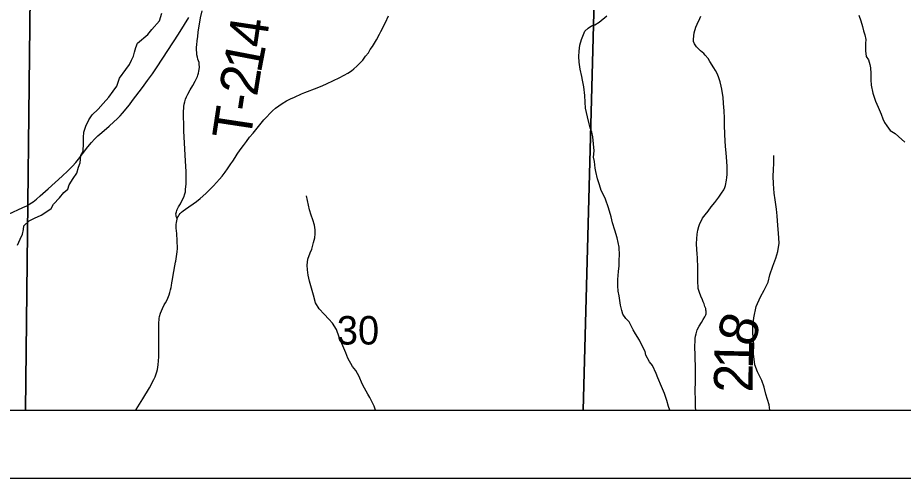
# Model space of a CAD drawing. Extents: x -19.9 to 41.9, y 0 to 32.3.
# Drawn here: x 4.967 to 6.268, y 14 to 14.677 of the extents above; entities that cross this region are included whole.
import ezdxf

# ---------------------------------------------------------------- set-up
doc = ezdxf.new("R2010")
doc.units = 0
for name, color, linetype in [('GM_X_Corporation', 7, 'Continuous'), ('GM_X_Minor_River', 7, 'Continuous'), ('GM_X_Section_Text', 7, 'Continuous'), ('GM_X_Township_Road', 7, 'Continuous'), ('GM_X_Township_Road_Text', 7, 'Continuous'), ('SH_Data', 7, 'Continuous')]:
    doc.layers.add(name, color=color, linetype=linetype)

msp = doc.modelspace()

# ---------------------------------------------------------------- linework, layer by layer
at = {"layer": 'GM_X_Corporation'}
for points in [[(2.1, 17.918), (2.1, 14.1), (8.9, 14.1), (8.9, 17.8974), (7.9072, 17.9171), (7.5529, 17.9242), (7.3858, 17.9277), (6.9468, 17.937), (6.7, 17.9422), (6.3069, 17.9505), (6.2497, 17.9517), (6.2397, 17.9517), (5.9048, 17.9534), (5.761, 17.9543), (5.4954, 17.9559), (5.0257, 17.9637), (5.0192, 17.8403), (4.9169, 17.8392), (4.2613, 17.8672), (3.984, 17.879), (3.7505, 17.884), (2.973, 17.9007), (2.4715, 17.9106)], [(4.9783, 14.1), (5.7974, 14.1), (5.8188, 14.9036), (4.9872, 14.9075), (4.9863, 14.8396)], [(5.7974, 14.1), (6.8053, 14.1), (6.8226, 14.894), (5.8188, 14.9036)], [(3.9655, 14.1), (4.9783, 14.1), (4.9863, 14.8396), (3.9837, 14.8466)]]:
    msp.add_lwpolyline(points, close=True, dxfattribs=at)
msp.add_lwpolyline([(2.1, 17.918), (2.1, 14.1), (7.8246, 14.1), (7.8518, 15.3043), (7.854, 15.4058), (7.8702, 16.1679), (7.8776, 16.5173), (7.9012, 17.4524), (7.9072, 17.9171)], dxfattribs=at)
at = {"layer": 'GM_X_Minor_River'}
for points in [[(4.9665, 14.3425), (4.9705, 14.3517), (4.9738, 14.3586), (4.9753, 14.3655), (4.9759, 14.3712), (4.9834, 14.3782), (4.9913, 14.3825), (5.0011, 14.3868), (5.0093, 14.3919), (5.0157, 14.3965), (5.0194, 14.4027), (5.028, 14.4123), (5.0343, 14.42), (5.0403, 14.4251), (5.0424, 14.4312), (5.048, 14.4408), (5.0535, 14.4485), (5.0561, 14.4573), (5.0586, 14.4638), (5.0596, 14.4744), (5.0629, 14.4802), (5.0635, 14.4924), (5.0634, 14.5008), (5.064, 14.5088), (5.0665, 14.5176), (5.0713, 14.5271), (5.0758, 14.5344), (5.0851, 14.5426), (5.0922, 14.5511), (5.1004, 14.5603), (5.1067, 14.5688), (5.1123, 14.5761), (5.1163, 14.588), (5.1255, 14.601), (5.1307, 14.6083), (5.134, 14.6145), (5.137, 14.6202), (5.138, 14.6263), (5.1402, 14.6332), (5.1428, 14.6397), (5.1577, 14.6521), (5.1637, 14.6598), (5.1748, 14.6722), (5.1785, 14.6836)], [(5.9247, 14.1), (5.9229, 14.1054), (5.9205, 14.1145), (5.9169, 14.1244), (5.9126, 14.1349), (5.9071, 14.1478), (5.9047, 14.1539), (5.8993, 14.1656), (5.8946, 14.1712), (5.8896, 14.181), (5.8884, 14.1864), (5.8852, 14.1928), (5.8802, 14.203), (5.8744, 14.2124), (5.8709, 14.2184), (5.865, 14.2298), (5.86, 14.235), (5.8558, 14.2414), (5.8542, 14.2464), (5.8522, 14.2547), (5.8501, 14.2684), (5.8488, 14.2752), (5.8483, 14.2828), (5.8482, 14.2923), (5.8492, 14.3041), (5.8502, 14.3122), (5.8504, 14.3209), (5.8507, 14.3278), (5.8502, 14.3396), (5.8473, 14.3532), (5.8441, 14.3646), (5.8406, 14.3756), (5.8385, 14.3843), (5.8346, 14.3976), (5.8302, 14.4104), (5.8279, 14.4157), (5.824, 14.4229), (5.8212, 14.4312), (5.8184, 14.44), (5.816, 14.451), (5.8152, 14.4559), (5.8139, 14.4658), (5.8126, 14.4718), (5.8133, 14.4814), (5.8127, 14.4916), (5.8115, 14.5019), (5.8102, 14.5087), (5.8079, 14.5152), (5.8063, 14.5212), (5.8038, 14.5311), (5.801, 14.544), (5.8005, 14.5527), (5.7996, 14.5626), (5.7983, 14.5755), (5.7966, 14.585), (5.7954, 14.5907), (5.793, 14.6013), (5.7917, 14.6116), (5.7908, 14.62), (5.7914, 14.6276), (5.7925, 14.6367), (5.795, 14.6451), (5.7997, 14.657), (5.8046, 14.6616), (5.8095, 14.6648), (5.8143, 14.6667), (5.8211, 14.6706), (5.8323, 14.6796)], [(6.2026, 14.6805), (6.2054, 14.6722), (6.2077, 14.6642), (6.2094, 14.6578), (6.2113, 14.6517), (6.2126, 14.6449), (6.2123, 14.6392), (6.212, 14.6342), (6.2121, 14.6281), (6.2133, 14.6201), (6.2164, 14.6149), (6.2184, 14.6084), (6.2196, 14.6031), (6.2201, 14.5951), (6.2202, 14.5856), (6.2207, 14.578), (6.2228, 14.5662), (6.2268, 14.5545), (6.2307, 14.5454), (6.235, 14.5352), (6.2377, 14.5284), (6.2401, 14.5227), (6.2436, 14.5178), (6.2486, 14.5114), (6.2555, 14.5066), (6.2605, 14.5025), (6.27, 14.4939)], [(6.0716, 14.1), (6.0705, 14.1079), (6.0659, 14.1235), (6.0633, 14.1341), (6.0598, 14.1436), (6.0537, 14.1565), (6.0495, 14.1668), (6.0476, 14.1827), (6.0479, 14.1968), (6.0468, 14.2131), (6.0464, 14.223), (6.0479, 14.2359), (6.0517, 14.2526), (6.0578, 14.2667), (6.0635, 14.2765), (6.0692, 14.2883), (6.0718, 14.299), (6.076, 14.3119), (6.0806, 14.3233), (6.0832, 14.3331), (6.0851, 14.3457), (6.0844, 14.3605), (6.0836, 14.3715), (6.0824, 14.3859), (6.0813, 14.3954), (6.0793, 14.4095), (6.0782, 14.4193), (6.077, 14.4326), (6.0766, 14.444), (6.077, 14.4535), (6.0774, 14.4634), (6.0774, 14.4744)], [(5.4924, 14.1), (5.4901, 14.1059), (5.4839, 14.1188), (5.4812, 14.1237), (5.4761, 14.1327), (5.4726, 14.1388), (5.4683, 14.1494), (5.4636, 14.1584), (5.4586, 14.1641), (5.4516, 14.1765), (5.4485, 14.1845), (5.4442, 14.1947), (5.4391, 14.2076), (5.4351, 14.2185), (5.4293, 14.228), (5.4235, 14.234), (5.417, 14.2411), (5.4093, 14.249), (5.4043, 14.258), (5.4011, 14.269), (5.3983, 14.2796), (5.3955, 14.2895), (5.3934, 14.2986), (5.3926, 14.3062), (5.3921, 14.3134), (5.3931, 14.3222), (5.3964, 14.3314), (5.3986, 14.3367), (5.4011, 14.3467), (5.4032, 14.3536), (5.4039, 14.3593), (5.4038, 14.3654), (5.4026, 14.3718), (5.4002, 14.3798), (5.3978, 14.3866), (5.3954, 14.3945), (5.3907, 14.4154)]]:
    msp.add_lwpolyline(points, dxfattribs=at)
at = {"layer": 'GM_X_Township_Road'}
for points in [[(4.9533, 14.3884), (4.9744, 14.398), (4.9799, 14.4006), (4.9845, 14.4033), (4.9892, 14.4063), (4.9941, 14.4102), (4.9995, 14.415), (5.0115, 14.4256), (5.0319, 14.444), (5.0401, 14.4517), (5.0472, 14.4586), (5.0521, 14.4642), (5.0561, 14.4689), (5.062, 14.4768), (5.0696, 14.487), (5.075, 14.4934), (5.0796, 14.4983), (5.0846, 14.5033), (5.0902, 14.5084), (5.1012, 14.5177), (5.1081, 14.5238), (5.113, 14.5285), (5.1171, 14.5328), (5.1205, 14.5367), (5.1307, 14.549), (5.1355, 14.5553), (5.15, 14.5746), (5.1574, 14.5845), (5.1646, 14.5944), (5.1715, 14.6046), (5.2031, 14.6526), (5.2119, 14.6668), (5.2182, 14.6773)], [(5.2009, 14.381), (5.2002, 14.3828), (5.1995, 14.3848), (5.1993, 14.3866), (5.1992, 14.3885), (5.1993, 14.3902), (5.1997, 14.3917), (5.2003, 14.3934), (5.201, 14.3949), (5.203, 14.3988), (5.2057, 14.4036), (5.2085, 14.409), (5.211, 14.4143), (5.2118, 14.4164), (5.2131, 14.4212), (5.2134, 14.4244), (5.2138, 14.4289), (5.214, 14.4323), (5.2141, 14.4349), (5.2143, 14.4388), (5.2141, 14.4439), (5.2139, 14.4502), (5.2131, 14.4665), (5.2109, 14.5103), (5.2107, 14.5163), (5.2102, 14.5359), (5.2104, 14.5399), (5.2105, 14.5435), (5.2106, 14.5466), (5.2111, 14.5501), (5.2121, 14.5534), (5.2133, 14.5574), (5.2147, 14.5608), (5.2165, 14.5645), (5.2199, 14.571), (5.2237, 14.5772), (5.2273, 14.5838), (5.2306, 14.5904), (5.2313, 14.5923), (5.2323, 14.5955), (5.2329, 14.5982), (5.2333, 14.601), (5.2336, 14.6042), (5.2334, 14.6088), (5.2331, 14.611), (5.2322, 14.6138), (5.2315, 14.6162), (5.2307, 14.6192), (5.23, 14.6223), (5.2296, 14.6251), (5.2294, 14.6295), (5.2295, 14.6339), (5.2297, 14.6371), (5.2302, 14.6431), (5.2311, 14.6494), (5.2318, 14.6558), (5.2331, 14.6649), (5.234, 14.6705), (5.2353, 14.6769), (5.2375, 14.6872)], [(5.4982, 14.653), (5.5, 14.6565), (5.5068, 14.6698), (5.5114, 14.6796)], [(5.9628, 14.1), (5.9626, 14.1045), (5.9623, 14.1095), (5.9622, 14.1162), (5.9621, 14.127), (5.9623, 14.1441), (5.9625, 14.1619), (5.9621, 14.1789), (5.9616, 14.1952), (5.9618, 14.201), (5.9619, 14.2054), (5.9625, 14.2087), (5.9633, 14.2123), (5.9649, 14.2181), (5.9677, 14.2237), (5.971, 14.229), (5.9739, 14.2333), (5.976, 14.2371), (5.9776, 14.2404), (5.9779, 14.2418), (5.9781, 14.2437), (5.978, 14.2456), (5.9778, 14.2472), (5.9775, 14.2498), (5.9762, 14.2527), (5.9749, 14.2563), (5.9737, 14.2592), (5.9725, 14.2625), (5.9702, 14.2679), (5.9684, 14.273), (5.9665, 14.2792), (5.9662, 14.2822), (5.9658, 14.2872), (5.9659, 14.2919), (5.9658, 14.3099), (5.9653, 14.3237), (5.9648, 14.3303), (5.9643, 14.336), (5.9641, 14.345), (5.9642, 14.3521), (5.9648, 14.3588), (5.9658, 14.3648), (5.9673, 14.3703), (5.9687, 14.3744), (5.9706, 14.378), (5.9728, 14.3822), (5.9764, 14.3871), (5.9808, 14.3926), (5.9853, 14.3988), (5.9907, 14.4053), (5.9965, 14.4131), (5.9979, 14.4149), (6.0007, 14.4191), (6.0038, 14.4241), (6.0054, 14.4274), (6.0064, 14.4302), (6.0072, 14.433), (6.0077, 14.4358), (6.0081, 14.4382), (6.0085, 14.4422), (6.0089, 14.4467), (6.009, 14.4522), (6.0089, 14.4583), (6.0085, 14.4656), (6.0075, 14.4784), (6.0067, 14.4879), (6.0057, 14.5047), (6.0051, 14.5198), (6.0048, 14.5295), (6.0044, 14.5402), (6.0036, 14.5509), (6.003, 14.56), (6.0022, 14.5655), (6.0011, 14.5719), (6.0002, 14.5764), (5.9987, 14.5829), (5.9962, 14.5901), (5.9941, 14.5949), (5.9916, 14.5995), (5.9892, 14.6035), (5.9835, 14.6128), (5.9808, 14.6168), (5.9768, 14.6218), (5.9745, 14.6243), (5.9723, 14.6264), (5.9699, 14.6284), (5.9673, 14.6308), (5.9641, 14.634), (5.9608, 14.6385), (5.9596, 14.642), (5.9594, 14.6456), (5.9603, 14.6547), (5.9631, 14.6631), (5.9649, 14.6673), (5.9687, 14.6758), (5.9704, 14.6793)], [(5.2009, 14.381), (5.2016, 14.3831), (5.2027, 14.3854), (5.204, 14.3874), (5.2053, 14.3891), (5.2071, 14.391), (5.2095, 14.3929), (5.2131, 14.3955), (5.2293, 14.4068), (5.2345, 14.4112), (5.243, 14.4188), (5.2483, 14.4239), (5.2543, 14.43), (5.2631, 14.4398), (5.2669, 14.4443), (5.2712, 14.4498), (5.2748, 14.4546), (5.28, 14.4623), (5.2825, 14.4662), (5.2861, 14.4716), (5.2893, 14.4762), (5.2936, 14.4826), (5.2983, 14.4893), (5.3026, 14.4952), (5.3074, 14.5014), (5.3124, 14.5074), (5.3283, 14.5269), (5.3325, 14.5313), (5.337, 14.5361), (5.3409, 14.5402), (5.3455, 14.544), (5.3501, 14.5473), (5.3553, 14.5509), (5.3617, 14.5546), (5.3672, 14.5576), (5.3732, 14.5604), (5.3835, 14.5649), (5.3887, 14.5671), (5.4064, 14.5738), (5.4149, 14.5774), (5.4205, 14.5799), (5.4306, 14.5845), (5.439, 14.5887), (5.4461, 14.5924), (5.4517, 14.5955), (5.457, 14.5989), (5.4607, 14.6017), (5.4649, 14.6055), (5.469, 14.6097), (5.4735, 14.6145), (5.4778, 14.6202), (5.4818, 14.6253), (5.4847, 14.63), (5.4877, 14.6346), (5.4936, 14.6442), (5.4982, 14.653)], [(5.1398, 14.1), (5.1406, 14.1013), (5.1505, 14.1169), (5.1602, 14.1331), (5.1667, 14.145), (5.1687, 14.1489), (5.1698, 14.152), (5.1712, 14.1566), (5.172, 14.1601), (5.1725, 14.1631), (5.1731, 14.1666), (5.1737, 14.1726), (5.1739, 14.1785), (5.174, 14.189), (5.1742, 14.2296), (5.1743, 14.2324), (5.1746, 14.2351), (5.1751, 14.2377), (5.1763, 14.2428), (5.1795, 14.2498), (5.182, 14.2548), (5.1839, 14.258), (5.1857, 14.2615), (5.187, 14.2648), (5.189, 14.2698), (5.19, 14.273), (5.1911, 14.2768), (5.1919, 14.2803), (5.1926, 14.2835), (5.1932, 14.2871), (5.1939, 14.2921), (5.1949, 14.2987), (5.1985, 14.3175), (5.1988, 14.3193), (5.2008, 14.3328), (5.2013, 14.3379), (5.2011, 14.3494), (5.201, 14.3523), (5.2005, 14.3566), (5.2002, 14.36), (5.1995, 14.3675), (5.1993, 14.3731), (5.1998, 14.376), (5.2003, 14.3786), (5.2009, 14.381)]]:
    msp.add_lwpolyline(points, dxfattribs=at)
at = {"layer": 'SH_Data'}
for p, q in [((2.1, 14.1), (8.9, 14.1)), ((2, 14), (9, 14))]:
    msp.add_line(p, q, dxfattribs=at)

# ---------------------------------------------------------------- texts
at = {"layer": 'GM_X_Section_Text'}
msp.add_text('30', height=0.04186, rotation=0, dxfattribs=at).set_placement((5.4354, 14.1966))
at = {"layer": 'GM_X_Township_Road_Text'}
for s, rotation, p in [('4', 81.5177, (5.3307, 14.6311)), ('1', 79.1422, (5.3237, 14.5942)), ('2', 80.8645, (5.3182, 14.5601)), ('-', 81.3025, (5.3147, 14.5372)), ('T', 81.3881, (5.3083, 14.4952)), ('8', 71.9225, (6.0465, 14.1908)), ('1', 88.678, (6.0465, 14.1604)), ('2', 89.7378, (6.0463, 14.126))]:
    msp.add_text(s, height=0.0568, rotation=rotation, dxfattribs=at).set_placement(p)

doc.saveas('drawing.dxf')
